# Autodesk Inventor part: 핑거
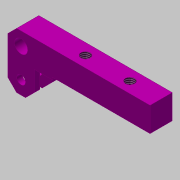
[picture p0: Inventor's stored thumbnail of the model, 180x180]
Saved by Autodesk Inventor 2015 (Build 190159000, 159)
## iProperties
Created: 2020-02
Part Number: 핑거
Material: 알루미늄 6061
Document SubType Name: Modeling
Designer: mduedu
Density: 1 g/cm^3
Appearance: 자홍색
Author: mduedu
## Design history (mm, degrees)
sketch "스케치1"
  geometry: L1 (0, 0)-(12, 0); L2 (64, 14)-(64, 25); L3 (64, 25)-(0, 25); L4 (0, 25)-(0, 0); L5 (12, 0)-(12, 13); L6 (12, 13)-(20, 13); L7 (64, 14)-(20, 14); L8 (20, 14)-(20, 13)
  constraints: 16 end point, 2 horizontal, 2 parallel, 1 perpendicular, 1 vertical
  dimensions: "d0" = 64 distance of L2.end L3.end; "d2" = 12 distance of L1.start L1.end; "d3" = 25 distance of L3.end L1.start; "d4" = 11 distance of L2.start L2.end; "d5" = 12 distance between parallel lines of L6 L3; "d6" = 44 distance of L2.start L7.end
extrude "돌출1" new body sketch "스케치1" stored distance "d7" = 10; taper "d8" = 0 deg
chamfer "모따기1" distance "d9" = 4; stored, may be unused: second distance "d10" = 2, angle "d11" = 45 deg
sketch "스케치2"
  geometry: L1 (2.5, -4)-(7.5, -4); L2 (7.5, -4)-(7.5, 9); L3 (7.5, 9)-(2.5, 9); L4 (2.5, 9)-(2.5, -4); L5 (10, 21)-(0, 21) reference; 2 further points
  constraints: 8 end point, 2 parallel, 1 coincident, 1 horizontal, 1 midpoint, 1 perpendicular
  dimensions: "d12" = 5 distance of L1.start L1.end; "d15" = 12 distance between parallel lines of L3 L5
extrude "돌출2" cut sketch "스케치2" stored distance "d16" = 10; taper "d17" = 0 deg
sketch "스케치3"
  geometry: L1 (0, 4)-(0, 21) reference; L2 (4, 25)-(64, 25) reference; C1 r 2 at (6, 6); C2 r 3 at (6, 19); 1 further point
  constraints: 2 centre point, 1 vertical alignment
  dimensions: "d18" = 6 distance from line of C2.centre L1; "d19" = 6 distance from line of C2.centre L2; "d20" = 13 distance of C1.centre C2.centre; "d21" = 6 diameter of C2; "d22" = 4 diameter of C1
extrude "돌출3" cut sketch "스케치3" stored distance "d23" = 10; taper "d24" = 0 deg
sketch "스케치4"
  geometry: L1 (0, 10)-(0, 0) reference; 3 further points
  constraints: 2 horizontal alignment
  dimensions: "d25" = 14 distance from line of point (-14, 5) L1; "d26" = 20 distance of point (-34, 5) point (-14, 5)
hole "구멍1" sketch "스케치4" at (-34, 5), (-14, 5) diameter "d27" = 4.134; stored, may be unused: countersink angle "d31" = 90 deg, drill point angle "d33" = 118 deg; dims "d28" = 6, "d29" = 4, "d30" = 2, "d32" = 8
node "솔리드1"
